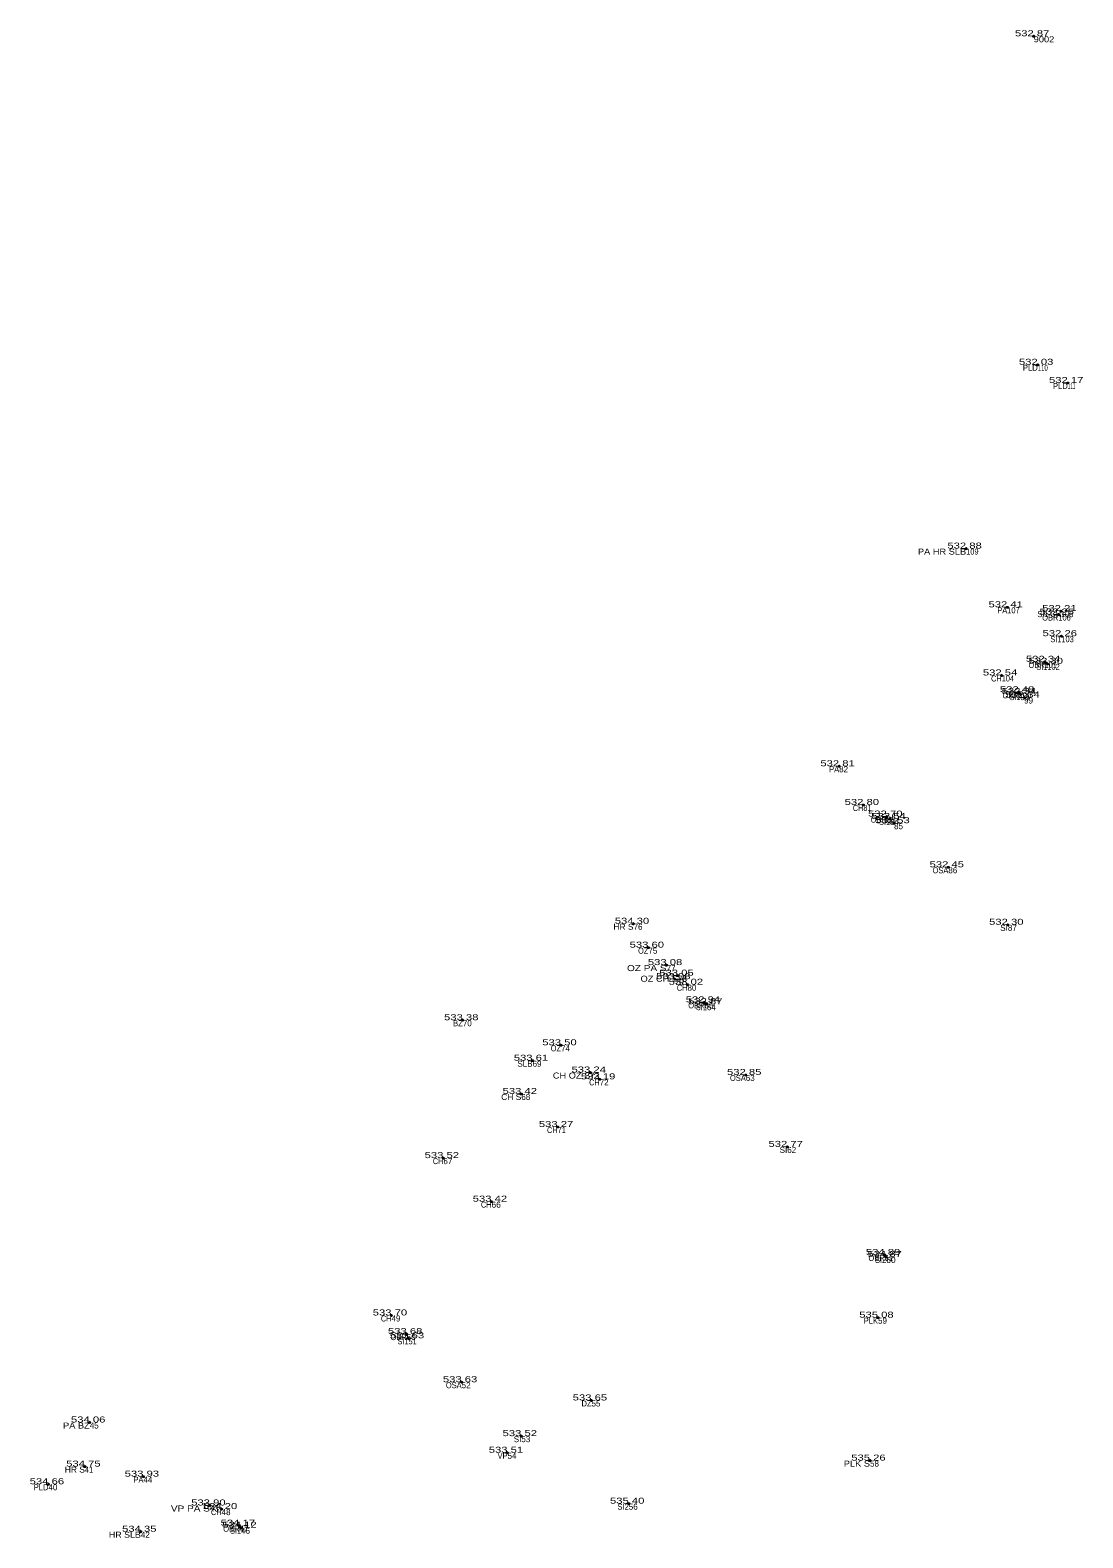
# Model space of a CAD drawing. Extents: x -643086 to -639283, y -1131805 to -1123269.
# Drawn here: x -642760.4 to -642707.8, y -1131119.6 to -1131044.4 of the extents above; entities that cross this region are included whole.
import ezdxf
from ezdxf.enums import TextEntityAlignment as Align

# ---------------------------------------------------------------- set-up
doc = ezdxf.new("R2010")
doc.units = 0
doc.header["$LTSCALE"] = 0.12
doc.header["$PDMODE"] = 32
doc.header["$PDSIZE"] = 0.06
for name, color, linetype in [('1', 7, 'Continuous'), ('2', 7, 'Continuous'), ('3', 7, 'Continuous'), ('4', 7, 'Continuous')]:
    doc.layers.add(name, color=color, linetype=linetype)

msp = doc.modelspace()

# ---------------------------------------------------------------- linework, layer by layer
at = {"layer": '1'}
for p in [(-642710.29, -1131044.69), (-642710.09, -1131061.08), (-642708.59, -1131061.99), (-642713.66, -1131070.25), (-642711.61, -1131073.18), (-642709.06, -1131073.54), (-642708.93, -1131073.37), (-642708.91, -1131074.62), (-642709.74, -1131075.9), (-642709.61, -1131076), (-642711.89, -1131076.58), (-642711.04, -1131077.42), (-642710.95, -1131077.51), (-642710.77, -1131077.68), (-642720, -1131081.11), (-642718.79, -1131083.04), (-642717.62, -1131083.62), (-642717.46, -1131083.74), (-642717.26, -1131083.95), (-642714.55, -1131086.15), (-642730.26, -1131088.97), (-642711.58, -1131089.02), (-642729.52, -1131090.16), (-642728.61, -1131091.03), (-642728.2, -1131091.73), (-642728.04, -1131091.56), (-642727.57, -1131092.01), (-642726.72, -1131092.89), (-642726.6, -1131092.98), (-642738.78, -1131093.78), (-642733.88, -1131095.03), (-642735.3, -1131095.8), (-642732.42, -1131096.39), (-642731.95, -1131096.73), (-642724.66, -1131096.51), (-642735.86, -1131097.46), (-642734.05, -1131099.11), (-642722.59, -1131100.1), (-642739.75, -1131100.66), (-642737.35, -1131102.83), (-642717.73, -1131105.49), (-642717.65, -1131105.59), (-642742.34, -1131108.51), (-642718.06, -1131108.62), (-642741.58, -1131109.44), (-642741.49, -1131109.65), (-642738.84, -1131111.84), (-642732.36, -1131112.75), (-642757.4, -1131113.85), (-642735.86, -1131114.53), (-642736.55, -1131115.36), (-642718.46, -1131115.75), (-642757.64, -1131116.05), (-642754.72, -1131116.55), (-642759.46, -1131116.93), (-642751.4, -1131117.99), (-642750.82, -1131118.17), (-642730.5, -1131117.9), (-642754.85, -1131119.3), (-642749.93, -1131119), (-642749.85, -1131119.1)]:
    msp.add_point(p, dxfattribs=at)

# ---------------------------------------------------------------- texts
at = {"layer": '2'}
for s, width, p in [('9002', 1.15, (-642710.29, -1131044.99)), ('110', 0.6, (-642710.09, -1131061.38)), ('111', 0.45, (-642708.59, -1131062.29)), ('109', 0.85, (-642713.66, -1131070.55)), ('107', 0.85, (-642711.61, -1131073.48)), ('106', 0.85, (-642709.06, -1131073.84)), ('105', 0.85, (-642708.93, -1131073.67)), ('103', 0.85, (-642708.91, -1131074.92)), ('101', 0.75, (-642709.74, -1131076.2)), ('102', 0.85, (-642709.61, -1131076.3)), ('104', 0.85, (-642711.89, -1131076.88)), ('100', 0.85, (-642711.04, -1131077.72)), ('81', 0.8, (-642718.79, -1131083.34)), ('71', 0.8, (-642734.05, -1131099.41)), ('66', 1.05, (-642737.35, -1131103.13)), ('61', 0.85, (-642717.73, -1131105.79)), ('60', 1.05, (-642717.65, -1131105.89)), ('51', 0.8, (-642741.49, -1131109.95)), ('41', 0.8, (-642757.64, -1131116.35))]:
    msp.add_text(s, height=0.3, dxfattribs=dict(at, width=width)).set_placement(p)
for s, p in [('98', (-642710.95, -1131077.81)), ('99', (-642710.77, -1131077.98)), ('82', (-642720, -1131081.41)), ('83', (-642717.62, -1131083.92)), ('84', (-642717.46, -1131084.04)), ('85', (-642717.26, -1131084.25)), ('86', (-642714.55, -1131086.45)), ('76', (-642730.26, -1131089.27)), ('87', (-642711.58, -1131089.32)), ('75', (-642729.52, -1131090.46)), ('77', (-642728.61, -1131091.33)), ('79', (-642728.2, -1131092.03)), ('78', (-642728.04, -1131091.86)), ('80', (-642727.57, -1131092.31)), ('65', (-642726.72, -1131093.19)), ('64', (-642726.6, -1131093.28)), ('70', (-642738.78, -1131094.08)), ('74', (-642733.88, -1131095.33)), ('69', (-642735.3, -1131096.1)), ('73', (-642732.42, -1131096.69)), ('72', (-642731.95, -1131097.03)), ('63', (-642724.66, -1131096.81)), ('68', (-642735.86, -1131097.76)), ('62', (-642722.59, -1131100.4)), ('67', (-642739.75, -1131100.96)), ('49', (-642742.34, -1131108.81)), ('59', (-642718.06, -1131108.92)), ('50', (-642741.58, -1131109.74)), ('52', (-642738.84, -1131112.14)), ('55', (-642732.36, -1131113.05)), ('45', (-642757.4, -1131114.15)), ('53', (-642735.86, -1131114.83)), ('54', (-642736.55, -1131115.66)), ('58', (-642718.46, -1131116.05)), ('44', (-642754.72, -1131116.85)), ('40', (-642759.46, -1131117.23)), ('43', (-642751.4, -1131118.29)), ('48', (-642750.82, -1131118.47)), ('56', (-642730.5, -1131118.2)), ('42', (-642754.85, -1131119.6)), ('47', (-642749.93, -1131119.3)), ('46', (-642749.85, -1131119.4))]:
    msp.add_text(s, height=0.3, dxfattribs=at).set_placement(p)
at = {"layer": '3', "width": 1.4}
for s, p in [('532 87 ', (-642710.29, -1131044.69)), ('532 03 ', (-642710.09, -1131061.08)), ('532 17 ', (-642708.59, -1131061.99)), ('532 88 ', (-642713.66, -1131070.25)), ('532 41 ', (-642711.61, -1131073.18)), ('532 25 ', (-642709.06, -1131073.54)), ('532 21 ', (-642708.93, -1131073.37)), ('532 26 ', (-642708.91, -1131074.62)), ('532 34 ', (-642709.74, -1131075.9)), ('532 30 ', (-642709.61, -1131076)), ('532 54 ', (-642711.89, -1131076.58)), ('532 48 ', (-642711.04, -1131077.42)), ('532 34 ', (-642710.95, -1131077.51)), ('532 34 ', (-642710.77, -1131077.68)), ('532 81 ', (-642720, -1131081.11)), ('532 80 ', (-642718.79, -1131083.04)), ('532 70 ', (-642717.62, -1131083.62)), ('532 54 ', (-642717.46, -1131083.74)), ('532 53 ', (-642717.26, -1131083.95)), ('532 45 ', (-642714.55, -1131086.15)), ('534 30 ', (-642730.26, -1131088.97)), ('532 30 ', (-642711.58, -1131089.02)), ('533 60 ', (-642729.52, -1131090.16)), ('533 08 ', (-642728.61, -1131091.03)), ('533 08 ', (-642728.2, -1131091.73)), ('533 05 ', (-642728.04, -1131091.56)), ('533 02 ', (-642727.57, -1131092.01)), ('532 94 ', (-642726.72, -1131092.89)), ('532 87 ', (-642726.6, -1131092.98)), ('533 38 ', (-642738.78, -1131093.78)), ('533 50 ', (-642733.88, -1131095.03)), ('533 61 ', (-642735.3, -1131095.8)), ('533 24 ', (-642732.42, -1131096.39)), ('532 85 ', (-642724.66, -1131096.51)), ('533 19 ', (-642731.95, -1131096.73)), ('533 42 ', (-642735.86, -1131097.46)), ('533 27 ', (-642734.05, -1131099.11)), ('532 77 ', (-642722.59, -1131100.1)), ('533 52 ', (-642739.75, -1131100.66)), ('533 42 ', (-642737.35, -1131102.83)), ('534 89 ', (-642717.73, -1131105.49)), ('534 87 ', (-642717.65, -1131105.59)), ('533 70 ', (-642742.34, -1131108.51)), ('535 08 ', (-642718.06, -1131108.62)), ('533 68 ', (-642741.58, -1131109.44)), ('533 63 ', (-642741.49, -1131109.65)), ('533 63 ', (-642738.84, -1131111.84)), ('533 65 ', (-642732.36, -1131112.75)), ('534 06 ', (-642757.4, -1131113.85)), ('533 52 ', (-642735.86, -1131114.53)), ('533 51 ', (-642736.55, -1131115.36)), ('534 75 ', (-642757.64, -1131116.05)), ('535 26 ', (-642718.46, -1131115.75)), ('534 66 ', (-642759.46, -1131116.93)), ('533 93 ', (-642754.72, -1131116.55)), ('533 90 ', (-642751.4, -1131117.99)), ('534 20 ', (-642750.82, -1131118.17)), ('535 40 ', (-642730.5, -1131117.9)), ('534 17 ', (-642749.93, -1131119)), ('534 12 ', (-642749.85, -1131119.1)), ('534 35 ', (-642754.85, -1131119.3))]:
    msp.add_text(s, height=0.3, dxfattribs=at).set_placement(p, align=Align.CENTER)
at = {"layer": '4'}
for s, width, p in [('PLD', 0.95, (-642710.09, -1131061.38)), ('PLD', 0.95, (-642708.59, -1131062.29)), ('PA HR SLB', 1.15, (-642713.66, -1131070.55)), ('PA', 0.9, (-642711.61, -1131073.48)), ('SI1 CH', 0.8, (-642708.93, -1131073.67)), ('OBR', 0.9, (-642709.06, -1131073.84)), ('SI1', 0.8, (-642708.91, -1131074.92)), ('OBR', 0.9, (-642709.74, -1131076.2)), ('SI1', 0.8, (-642709.61, -1131076.3)), ('CH', 0.8, (-642711.89, -1131076.88)), ('OBR', 0.9, (-642711.04, -1131077.72)), ('SI1', 0.8, (-642710.95, -1131077.81)), ('PA', 0.9, (-642720, -1131081.41)), ('CH', 0.8, (-642718.79, -1131083.34)), ('OBR', 0.9, (-642717.62, -1131083.92)), ('SI1', 0.8, (-642717.46, -1131084.04)), ('OSA', 0.9, (-642714.55, -1131086.45)), ('HR S', 1.05, (-642730.26, -1131089.27)), ('OZ', 0.85, (-642729.52, -1131090.46)), ('OZ PA S', 1.25, (-642728.61, -1131091.33)), ('OZ CH S', 1.15, (-642728.04, -1131091.86)), ('CH', 0.8, (-642727.57, -1131092.31)), ('OBR', 0.9, (-642726.72, -1131093.19)), ('SI1', 0.8, (-642726.6, -1131093.28)), ('BZ', 0.95, (-642738.78, -1131094.08)), ('OZ', 0.85, (-642733.88, -1131095.33)), ('CH OZ S', 1.15, (-642732.42, -1131096.69)), ('CH', 0.8, (-642731.95, -1131097.03)), ('OSA', 0.9, (-642724.66, -1131096.81)), ('CH S', 1.05, (-642735.86, -1131097.76)), ('CH', 0.8, (-642734.05, -1131099.41)), ('CH', 0.8, (-642739.75, -1131100.96)), ('CH', 0.8, (-642737.35, -1131103.13)), ('OBR', 0.9, (-642717.73, -1131105.79)), ('SI2', 0.9, (-642717.65, -1131105.89)), ('CH', 0.8, (-642742.34, -1131108.81)), ('PLK', 0.95, (-642718.06, -1131108.92)), ('OBR', 0.9, (-642741.58, -1131109.74)), ('SI1', 0.8, (-642741.49, -1131109.95)), ('OSA', 0.9, (-642738.84, -1131112.14)), ('DZ', 0.9, (-642732.36, -1131113.05)), ('PA BZ', 1.15, (-642757.4, -1131114.15)), ('VP', 0.9, (-642736.55, -1131115.66)), ('PLK S', 1.15, (-642718.46, -1131116.05)), ('HR S', 1.05, (-642757.64, -1131116.35)), ('PA', 0.9, (-642754.72, -1131116.85)), ('PLD', 0.95, (-642759.46, -1131117.23)), ('VP PA S', 1.25, (-642751.4, -1131118.29)), ('CH', 0.8, (-642750.82, -1131118.47)), ('SI2', 0.9, (-642730.5, -1131118.2)), ('HR SLB', 1.1, (-642754.85, -1131119.6)), ('OBR', 0.9, (-642749.93, -1131119.3)), ('SI1', 0.8, (-642749.85, -1131119.4))]:
    msp.add_text(s, height=0.3, dxfattribs=dict(at, width=width)).set_placement(p, align=Align.RIGHT)
for s, p in [('SI', (-642711.58, -1131089.32)), ('SLB', (-642735.3, -1131096.1)), ('SI', (-642722.59, -1131100.4)), ('SI', (-642735.86, -1131114.83))]:
    msp.add_text(s, height=0.3, dxfattribs=at).set_placement(p, align=Align.RIGHT)

doc.saveas('drawing.dxf')
